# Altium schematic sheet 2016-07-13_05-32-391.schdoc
size 220 x 113 mm; SheetNumber: 1; SheetTotal: 1
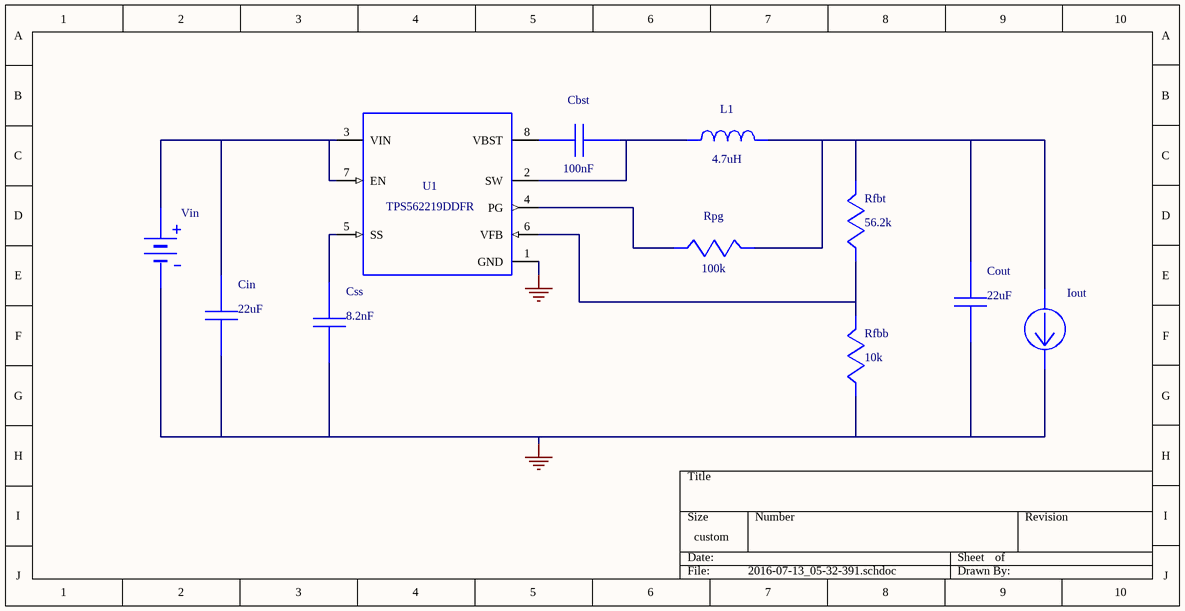
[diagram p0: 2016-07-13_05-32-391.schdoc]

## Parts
Cbst  value 100nF  (hidden comment: 08053C104KAT2A)
Cin  value 22uF  (hidden comment: GRM32ER61E226KE15L)
Cout  value 22uF  (hidden comment: GRM31CR61A226KE19L)
Css  value 8.2nF  (hidden comment: GRM033R61A822KA01D)
Iout  WB_CURRENT_LOAD  (value not drawn)
L1  value 4.7uH  (hidden comment: SRN6045-4R7Y)
Rfbb  value 10k  (hidden comment: CRCW040210K0FKED)
Rfbt  value 56.2k  (hidden comment: CRCW040256K2FKED)
Rpg  value 100k  (hidden comment: CRCW0402100KFKED)
U1  TPS562219DDFR
Vin  WB_BATTERY  (value not drawn)

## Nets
0: Cin.2 Cout.2 Css.2 Iout.2(-) Rfbb.2 U1.1(GND) Vin.2(-)
NetCbst_1: Cbst.1 L1.2 U1.2(SW)
NetCbst_2: Cbst.2 U1.8(VBST)
NetCin_1: Cin.1 U1.3(VIN) U1.7(EN) Vin.1(+)
NetCout_1: Cout.1 Iout.1(+) L1.1 Rfbt.1 Rpg.1
NetCss_1: Css.1 U1.5(SS)
NetRfbb_1: Rfbb.1 Rfbt.2 U1.6(VFB)
NetRpg_2: Rpg.2 U1.4(PG)

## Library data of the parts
Cbst = 08053C104KAT2A: Manufacturer Name: AVX
Cin = GRM32ER61E226KE15L: GRM32ER61E226KE1; Manufacturer Name: MuRata
Cout = GRM31CR61A226KE19L: GRM31CR61A226KE1; Manufacturer Name: MuRata
Css = GRM033R61A822KA01D: GRM033R61A822KA0; Manufacturer Name: MuRata
L1 = SRN6045-4R7Y: Manufacturer Name: Bourns
Rfbb = CRCW040210K0FKED: Manufacturer Name: Vishay-Dale
Rfbt = CRCW040256K2FKED: Manufacturer Name: Vishay-Dale
Rpg = CRCW0402100KFKED: Manufacturer Name: Vishay-Dale
U1 = TPS562219DDFR: Manufacturer Name: Texas Instruments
